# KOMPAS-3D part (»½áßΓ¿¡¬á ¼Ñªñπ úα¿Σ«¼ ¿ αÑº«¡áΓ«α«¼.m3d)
File: created 06.11.2015 16:49:14, last saved 22.07.2016 14:57:03.
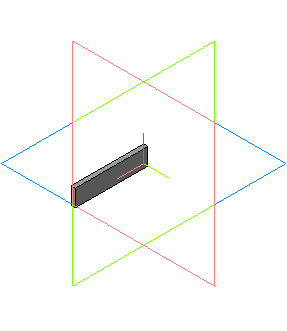
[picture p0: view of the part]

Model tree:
1. Эскиз:1
2. Операция выдавливания:1
     Расстояние 1 = 6
3. Эскиз:2
4. Вырезать элемент выдавливания:1
     Толщина стенки 2 = 1.5; Расстояние 1 = 21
